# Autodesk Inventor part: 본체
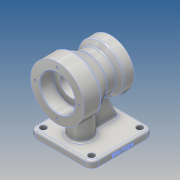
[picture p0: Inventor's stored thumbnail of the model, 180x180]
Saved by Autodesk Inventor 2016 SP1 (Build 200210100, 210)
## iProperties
Created: 2019-01
Part Number: 본체
Material: 알루미늄 6061
Document SubType Name: Modeling
Designer: Administrator
Density: 2.7 g/cm^3
Appearance: 알루미늄 - 평지
Author: Administrator
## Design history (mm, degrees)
sketch "스케치2"
  geometry: L1 (0, 0)-(-80, 0); L2 (0, 0)-(0, 40); L3 (0, 40)-(-25, 40); L4 (-25, 40)-(-45.785, 28); L5 (-45.785, 28)-(-59.126, 28); L6 (-59.126, 28)-(-65, 35); L7 (-65, 35)-(-80, 35); L8 (-80, 35)-(-80, 0)
  constraints: 16 end point, 2 parallel, 2 perpendicular, 1 horizontal, 1 vertical
  dimensions: "d0" = 80 distance of L1.start L1.end; "d1" = 80 diameter of L3 L1; "d2" = 30 deg angle of L5 L4; "d3" = 50 deg angle of L5 L6; "d4" = 25 distance of L2.end L3.end; "d5" = 56 diameter of L5 L1; "d6" = 15 distance of L6.end L7.end; "d7" = 70 diameter of L7 L1
revolve "회전1" sketch "스케치2" stored, may be unused: angle "d8" = 90 deg
node "작업 평면1"
sketch "스케치4"
  geometry: L1 (5, 46)-(97, 46); L2 (97, 46)-(97, -46); L3 (97, -46)-(5, -46); L4 (5, -46)-(5, 46); 2 further points
  constraints: 8 end point, 2 parallel, 1 horizontal, 1 horizontal alignment, 1 midpoint, 1 perpendicular
  dimensions: "d12" = 92 distance of L2.end L3.end; "d13" = 92 distance of L1.end L2.end; "d14" = 5 distance from line of point (0, 0) L4
extrude "돌출1" join sketch "스케치4" distance "d15" = 10; taper "d16" = 0 deg
sketch "스케치5"
  geometry: L1 (50.199, 5)-(87, 5); L2 (87, 5)-(87, -5); L3 (87, -5)-(50.199, -5); L4 (5, -46)-(5, 46) reference; L5 (97, 46)-(97, -46) reference; A1 r 16 centre (35, 0) between (50.199, 5) and (50.199, -5); 2 further points
  constraints: 6 end point, 2 horizontal alignment, 2 point on circle, 1 centre point, 1 horizontal, 1 midpoint, 1 parallel, 1 perpendicular
  dimensions: "d17" = 32 diameter of A1; "d18" = 10 distance between parallel lines of L3 L1; "d19" = 30 distance from line of A1.centre L4; "d20" = 10 distance between parallel lines of L2 L5
extrude "돌출2" join sketch "스케치5" distance "d21" = 45; taper "d22" = 0 deg
feature "면 기울기2" dims angle "d26" = 25 deg
sketch "스케치7"
  geometry: L1 (0, 0)-(-80, 0); L2 (-80, -35)-(-80, 35) reference; L3 (0, -40)-(0, 40) reference; L4 (0, 26)-(-19, 26); L5 (-20, 25)-(-20, 16); L6 (-20, 16)-(-63, 16); L7 (-63, 16)-(-63, 19.4); L8 (-63.6, 20)-(-80, 20); L9 (0, 26)-(0, 0); L10 (-80, 20)-(-80, 0); A1 r 1 centre (-19, 25) between (-19, 26) and (-20, 25); A2 r 0.6 centre (-63.6, 19.4) between (-63, 19.4) and (-63.6, 20); 2 further points
  constraints: 16 end point, 6 point on line, 4 perpendicular, 4 point on circle, 4 tangent, 2 centre point, 1 collinear, 1 horizontal, 1 midpoint, 1 parallel
  dimensions: "d27" = 52 diameter of L4 L1; "d28" = 20 distance of L4.start point (-20, 26); "d29" = 32 diameter of L6 L1; "d30" = 17 distance of point (-63, 20) L8.end; "d31" = 40 diameter of L8 L1; "d32" = 1 radius of A1; "d33" = 0.6 radius of A2
revolve "회전2" sketch "스케치7" stored, may be unused: angle "d34" = 90 deg
sketch "스케치8" dims "d35" = 66
  geometry: 3 further points
  constraints: 2 horizontal alignment, 1 coincident, 2 other
hole "구멍1" sketch "스케치8" at (33, 0) diameter "d36" = 3.242; stored, may be unused: countersink angle "d40" = 90 deg, drill point angle "d42" = 118 deg; dims "d37" = 9, "d38" = 4, "d39" = 2, "d41" = 11
sketch "스케치9" dims "d46" = 55
  geometry: 3 further points
  constraints: 2 horizontal alignment, 1 coincident, 2 other
hole "구멍2" sketch "스케치9" at (-27.5, 0) diameter "d47" = 3.242; stored, may be unused: countersink angle "d51" = 90 deg, drill point angle "d53" = 118 deg; dims "d48" = 9, "d49" = 4, "d50" = 2, "d52" = 11
fillet "모깎기1" dims "d57" = 10, "d58" = 3, "d59" = 3, "d60" = 3, "d61" = 3
sketch "스케치10"
  geometry: L1 (97, 36)-(97, -36) reference; L2 (87, -46)-(15, -46) reference; L3 (5, -36)-(5, 36) reference; L4 (15, 46)-(87, 46) reference; C1 r 4.5 at (15, 36); C2 r 4.5 at (87, 36); C3 r 4.5 at (87, -36); C4 r 4.5 at (15, -36); A1 r 10 centre (87, 36) between (97, 36) and (87, 46) reference; A2 r 10 centre (87, -36) between (87, -46) and (97, -36) reference; A3 r 10 centre (15, -36) between (5, -36) and (15, -46) reference; A4 r 10 centre (15, 36) between (15, 46) and (5, 36) reference; 1 further point
  constraints: 4 centre point, 4 coincident
  dimensions: "d62" = 9 diameter of C1; "d63" = 9 diameter of C2; "d64" = 9 diameter of C3; "d65" = 9 diameter of C4
extrude "돌출3" cut sketch "스케치10" stored distance "d66" = 45; taper "d67" = 0 deg
chamfer "모따기1" distance "d68" = 1; stored, may be unused: second distance "d69" = 2, angle "d70" = 45 deg
fillet "모깎기2" dims "d71" = 3
sketch "스케치11"
  geometry: L1 (72, 0)-(0, 0) reference; L2 (-10, 7)-(-10, 0) reference; 2 further points
  constraints: 1 other
  dimensions: "d72" = 4 distance from line of L1 point (36, 4); "d73" = 46 distance from line of L2 point (36, 4)
feature "엠보싱1" sketch "스케치11" dims "d17" = 32, "d18" = 10, "d19" = 30, "d20" = 10, "d74" = 0.5, "d75" = 0
node "솔리드1"
pattern_circular "원형 패턴1" dims angle "d44" = 360 deg
pattern_circular "원형 패턴2" dims angle "d55" = 360 deg
node "투영된 루프1"
